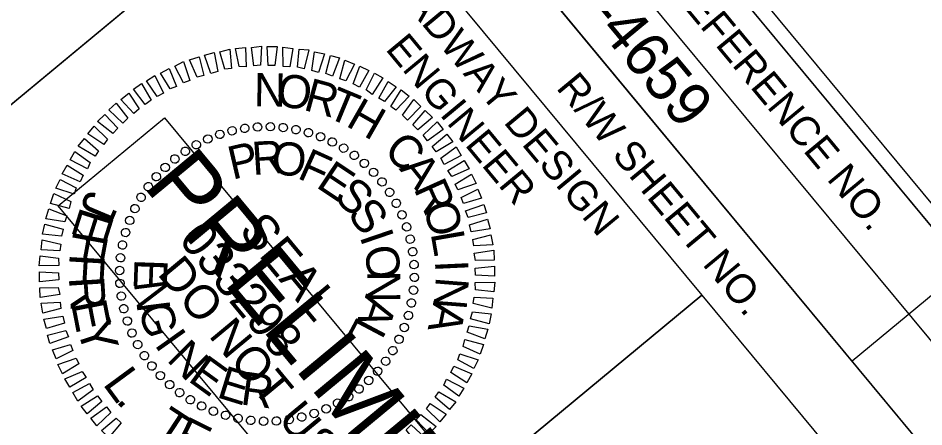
# Model space of a CAD drawing. Extents: x 2057815 to 2059783, y 687683 to 689713.
# Drawn here: x 2059495.3 to 2059649.4, y 688411.4 to 688481 of the extents above; entities that cross this region are included whole.
import ezdxf

# ---------------------------------------------------------------- set-up
doc = ezdxf.new("R2010")
doc.units = 0
for name, color, linetype in [('Sheet Data Field CELL', 7, 'Continuous'), ('Sheet Plan CELL', 7, 'Continuous'), ('Sheet Plan Layout CELL', 7, 'Continuous'), ('Sheet Plot Border Inside CELL', 7, 'Continuous'), ('Sheet Professional Seal CELL', 7, 'Continuous'), ('Sheet Sticker Preliminary CELL', 7, 'Continuous')]:
    doc.layers.add(name, color=color, linetype=linetype)

msp = doc.modelspace()

# ---------------------------------------------------------------- linework, layer by layer
at = {"layer": 'Sheet Plan CELL'}
for p, q in [((2059567.06, 688526.83), (2059694.75, 688372.83)), ((2059557.41, 688518.82), (2059685.12, 688364.85)), ((2059557.41, 688518.82), (2059685.12, 688364.85)), ((2059656.47, 688438.56), (2059637.26, 688422.56)), ((2059611.67, 688433.83), (2059525.11, 688362.04))]:
    msp.add_line(p, q, dxfattribs=at)
for points in [[(2059704.43, 688380.81), (2058746.91, 689535.49), (2057938.66, 688865.25), (2058896.16, 687710.59)], [(2057938.66, 688865.25), (2058746.88, 689535.49), (2059576.73, 688534.83), (2059461.22, 688439.03), (2059588.9, 688285.05), (2058896.16, 687710.59)], [(2059576.73, 688534.83), (2059704.43, 688380.81), (2059685.12, 688364.85), (2059557.41, 688518.82)], [(2059547.8, 688510.85), (2059611.67, 688433.83), (2059525.06, 688362.01), (2059461.22, 688439.03)], [(2059611.67, 688433.83), (2059675.5, 688356.87), (2059588.9, 688285.05), (2059525.06, 688362.01)]]:
    msp.add_lwpolyline(points, close=True, dxfattribs=at)
at = {"layer": 'Sheet Plan Layout CELL'}
msp.add_lwpolyline([(2059388.89, 688430.01), (2059541.63, 688245.83), (2059704.44, 688380.81), (2059551.69, 688565.01)], close=True, dxfattribs=at)
at = {"layer": 'Sheet Plot Border Inside CELL'}
msp.add_lwpolyline([(2057838.75, 688981.79), (2058902.21, 687699.38), (2059714.31, 688372.8), (2058650.85, 689655.23)], close=True, dxfattribs=at)
at = {"layer": 'Sheet Professional Seal CELL'}
for p, q in [((2059536.04, 688462.48), (2059536.04, 688462.48)), ((2059538.25, 688462.56), (2059538.25, 688462.56)), ((2059529.61, 688461.23), (2059529.61, 688461.23)), ((2059531.72, 688461.82), (2059531.72, 688461.82)), ((2059533.86, 688462.29), (2059533.86, 688462.29)), ((2059540.4, 688462.39), (2059540.4, 688462.39)), ((2059542.61, 688462.08), (2059542.61, 688462.08)), ((2059544.69, 688461.53), (2059544.69, 688461.53)), ((2059525.64, 688459.44), (2059525.64, 688459.44)), ((2059527.54, 688460.43), (2059527.54, 688460.43)), ((2059546.79, 688460.8), (2059546.79, 688460.8)), ((2059548.8, 688459.94), (2059548.8, 688459.94)), ((2059523.76, 688458.33), (2059523.76, 688458.33)), ((2059550.7, 688458.91), (2059550.7, 688458.91)), ((2059521.97, 688457.04), (2059521.97, 688457.04)), ((2059552.5, 688457.68), (2059552.5, 688457.68)), ((2059520.31, 688455.6), (2059520.31, 688455.6)), ((2059554.21, 688456.24), (2059554.21, 688456.24)), ((2059555.81, 688454.77), (2059555.81, 688454.77)), ((2059518.85, 688454), (2059518.85, 688454)), ((2059517.41, 688452.29), (2059517.41, 688452.29)), ((2059557.26, 688453.11), (2059557.26, 688453.11)), ((2059516.18, 688450.48), (2059516.18, 688450.48)), ((2059558.55, 688451.32), (2059558.55, 688451.32)), ((2059515.15, 688448.59), (2059515.15, 688448.59)), ((2059559.65, 688449.44), (2059559.65, 688449.44)), ((2059560.64, 688447.54), (2059560.64, 688447.54)), ((2059514.29, 688446.58), (2059514.29, 688446.58)), ((2059561.44, 688445.48), (2059561.44, 688445.48)), ((2059513.56, 688444.48), (2059513.56, 688444.48)), ((2059513.01, 688442.4), (2059513.01, 688442.4)), ((2059562.03, 688443.36), (2059562.03, 688443.36)), ((2059562.5, 688441.22), (2059562.5, 688441.22)), ((2059512.69, 688440.19), (2059512.69, 688440.19)), ((2059512.53, 688438.04), (2059512.53, 688438.04)), ((2059562.69, 688439.04), (2059562.69, 688439.04)), ((2059537.65, 688437.44), (2059537.65, 688437.44)), ((2059562.77, 688436.83), (2059562.77, 688436.83)), ((2059512.61, 688435.83), (2059512.61, 688435.83)), ((2059562.6, 688434.68), (2059562.6, 688434.68)), ((2059512.79, 688433.65), (2059512.79, 688433.65)), ((2059562.29, 688432.47), (2059562.29, 688432.47)), ((2059513.27, 688431.51), (2059513.27, 688431.51)), ((2059561.74, 688430.39), (2059561.74, 688430.39)), ((2059513.85, 688429.4), (2059513.85, 688429.4)), ((2059514.65, 688427.33), (2059514.65, 688427.33)), ((2059561.01, 688428.3), (2059561.01, 688428.3)), ((2059560.15, 688426.28), (2059560.15, 688426.28)), ((2059515.65, 688425.43), (2059515.65, 688425.43)), ((2059559.12, 688424.39), (2059559.12, 688424.39)), ((2059516.75, 688423.55), (2059516.75, 688423.55)), ((2059557.89, 688422.59), (2059557.89, 688422.59)), ((2059518.04, 688421.76), (2059518.04, 688421.76)), ((2059556.45, 688420.87), (2059556.45, 688420.87)), ((2059519.48, 688420.1), (2059519.48, 688420.1)), ((2059554.99, 688419.27), (2059554.99, 688419.27)), ((2059521.09, 688418.64), (2059521.09, 688418.64)), ((2059553.32, 688417.83), (2059553.32, 688417.83)), ((2059522.8, 688417.2), (2059522.8, 688417.2)), ((2059551.54, 688416.54), (2059551.54, 688416.54)), ((2059524.6, 688415.96), (2059524.6, 688415.96)), ((2059526.49, 688414.94), (2059526.49, 688414.94)), ((2059549.66, 688415.44), (2059549.66, 688415.44)), ((2059528.51, 688414.07), (2059528.51, 688414.07)), ((2059530.61, 688413.34), (2059530.61, 688413.34)), ((2059545.69, 688413.64), (2059545.69, 688413.64)), ((2059547.75, 688414.44), (2059547.75, 688414.44)), ((2059532.69, 688412.79), (2059532.69, 688412.79)), ((2059534.89, 688412.48), (2059534.89, 688412.48)), ((2059537.04, 688412.32), (2059537.04, 688412.32)), ((2059539.25, 688412.39), (2059539.25, 688412.39)), ((2059541.44, 688412.58), (2059541.44, 688412.58)), ((2059543.58, 688413.06), (2059543.58, 688413.06))]:
    msp.add_line(p, q, dxfattribs=at)
for points in [[(2059528.09, 688471.6), (2059527, 688474.72), (2059528.67, 688475.13), (2059529.26, 688471.92)], [(2059530.5, 688472.3), (2059529.64, 688475.29), (2059531.31, 688475.7), (2059531.61, 688472.44)], [(2059532.92, 688472.75), (2059532.29, 688475.86), (2059534, 688475.98), (2059534.12, 688472.71)], [(2059535.42, 688472.87), (2059535, 688476.03), (2059536.72, 688476.23), (2059536.56, 688472.98)], [(2059537.84, 688472.93), (2059537.68, 688476.17), (2059539.38, 688476.16), (2059538.98, 688472.96)], [(2059540.42, 688472.79), (2059540.37, 688476.07), (2059542.05, 688475.84), (2059541.54, 688472.69)], [(2059542.82, 688472.64), (2059543.11, 688475.74), (2059544.8, 688475.58), (2059543.96, 688472.36)], [(2059545.29, 688472.09), (2059545.76, 688475.28), (2059547.43, 688474.91), (2059546.39, 688471.77)], [(2059523.43, 688470.01), (2059521.95, 688472.81), (2059523.45, 688473.6), (2059524.5, 688470.37)], [(2059525.76, 688470.97), (2059524.47, 688473.93), (2059526.08, 688474.42), (2059526.92, 688471.21)], [(2059547.65, 688471.59), (2059548.44, 688474.64), (2059550, 688474.24), (2059548.82, 688471.12)], [(2059550.02, 688470.69), (2059550.92, 688473.84), (2059552.52, 688473.15), (2059551.09, 688470.34)], [(2059521.17, 688468.98), (2059519.5, 688471.62), (2059521.03, 688472.44), (2059522.23, 688469.34)], [(2059552.32, 688469.8), (2059553.45, 688472.82), (2059554.98, 688472.07), (2059553.37, 688469.24)], [(2059518.95, 688467.66), (2059517.14, 688470.31), (2059518.58, 688471.25), (2059520.04, 688468.23)], [(2059554.53, 688468.78), (2059555.93, 688471.63), (2059557.35, 688470.86), (2059555.56, 688468.01)], [(2059556.71, 688467.4), (2059558.28, 688470.2), (2059559.62, 688469.3), (2059557.65, 688466.82)], [(2059516.94, 688466.32), (2059514.95, 688468.89), (2059516.28, 688469.86), (2059517.93, 688467.01)], [(2059558.74, 688465.97), (2059560.5, 688468.79), (2059561.85, 688467.7), (2059559.6, 688465.32)], [(2059514.99, 688464.76), (2059512.8, 688467.17), (2059514.11, 688468.25), (2059515.91, 688465.53)], [(2059560.7, 688464.47), (2059562.65, 688467.13), (2059563.82, 688465.96), (2059561.58, 688463.65)], [(2059513.1, 688463.13), (2059510.71, 688465.38), (2059511.96, 688466.54), (2059513.96, 688463.97)], [(2059511.44, 688461.37), (2059508.83, 688463.42), (2059510.04, 688464.62), (2059512.24, 688462.29)], [(2059562.46, 688462.82), (2059564.57, 688465.28), (2059565.81, 688464.1), (2059563.34, 688461.99)], [(2059509.88, 688459.49), (2059507.14, 688461.31), (2059508.25, 688462.62), (2059510.5, 688460.39)], [(2059564.25, 688461.05), (2059566.59, 688463.32), (2059567.61, 688462.02), (2059564.98, 688460.1)], [(2059565.74, 688459.17), (2059568.24, 688461.25), (2059569.26, 688459.95), (2059566.47, 688458.22)], [(2059508.42, 688457.49), (2059505.49, 688459.22), (2059506.57, 688460.51), (2059509, 688458.43)], [(2059507.08, 688455.35), (2059504.13, 688456.86), (2059504.97, 688458.28), (2059507.57, 688456.4)], [(2059567.22, 688457.15), (2059569.85, 688459.07), (2059570.67, 688457.61), (2059567.83, 688456.1)], [(2059568.45, 688455.05), (2059571.2, 688456.75), (2059572.06, 688455.32), (2059569.1, 688454.03)], [(2059505.84, 688453.15), (2059502.81, 688454.47), (2059503.62, 688455.99), (2059506.37, 688454.24)], [(2059504.83, 688451.01), (2059501.69, 688452.05), (2059502.47, 688453.54), (2059505.18, 688452.08)], [(2059569.65, 688452.74), (2059572.47, 688454.43), (2059573.25, 688452.86), (2059570.13, 688451.77)], [(2059570.68, 688450.47), (2059573.55, 688451.88), (2059574.15, 688450.36), (2059571.08, 688449.44)], [(2059503.96, 688448.61), (2059500.81, 688449.43), (2059501.36, 688451.12), (2059504.29, 688449.78)], [(2059571.43, 688448.17), (2059574.58, 688449.29), (2059575.02, 688447.83), (2059571.89, 688447.06)], [(2059503.22, 688446.3), (2059500.04, 688446.84), (2059500.54, 688448.5), (2059503.56, 688447.36)], [(2059502.67, 688443.9), (2059499.47, 688444.23), (2059499.84, 688445.9), (2059502.99, 688445.07)], [(2059572.13, 688445.83), (2059575.2, 688446.75), (2059575.65, 688445.11), (2059572.41, 688444.63)], [(2059572.71, 688443.32), (2059575.77, 688444.1), (2059576.07, 688442.41), (2059572.86, 688442.21)], [(2059502.4, 688441.4), (2059499.22, 688441.56), (2059499.38, 688443.25), (2059502.54, 688442.49)], [(2059572.92, 688440.96), (2059576.27, 688441.47), (2059576.29, 688439.8), (2059573.16, 688439.73)], [(2059502.21, 688438.9), (2059498.9, 688438.82), (2059499.05, 688440.51), (2059502.18, 688440.11)], [(2059502.23, 688436.45), (2059498.93, 688436.12), (2059498.94, 688437.82), (2059502.16, 688437.62)], [(2059573.07, 688438.43), (2059576.37, 688438.76), (2059576.35, 688437.05), (2059573.14, 688437.25)], [(2059502.38, 688433.91), (2059499.03, 688433.41), (2059499.01, 688435.08), (2059502.14, 688435.14)], [(2059573.09, 688435.97), (2059576.4, 688436.06), (2059576.24, 688434.37), (2059573.12, 688434.76)], [(2059572.89, 688433.47), (2059576.08, 688433.32), (2059575.92, 688431.63), (2059572.76, 688432.38)], [(2059502.58, 688431.55), (2059499.53, 688430.77), (2059499.23, 688432.47), (2059502.44, 688432.66)], [(2059503.17, 688429.04), (2059500.1, 688428.12), (2059499.65, 688429.76), (2059502.89, 688430.24)], [(2059572.63, 688430.98), (2059575.83, 688430.64), (2059575.46, 688428.97), (2059572.3, 688429.8)], [(2059572.08, 688428.58), (2059575.26, 688428.03), (2059574.75, 688426.37), (2059571.73, 688427.51)], [(2059503.87, 688426.71), (2059500.71, 688425.58), (2059500.28, 688427.04), (2059503.41, 688427.81)], [(2059504.62, 688424.4), (2059501.75, 688423), (2059501.15, 688424.51), (2059504.22, 688425.43)], [(2059571.33, 688426.27), (2059574.49, 688425.44), (2059573.94, 688423.75), (2059571.01, 688425.09)], [(2059505.65, 688422.14), (2059502.83, 688420.45), (2059502.05, 688422.01), (2059505.17, 688423.1)], [(2059570.47, 688423.86), (2059573.6, 688422.82), (2059572.83, 688421.33), (2059570.12, 688422.79)], [(2059506.85, 688419.82), (2059504.1, 688418.13), (2059503.24, 688419.56), (2059506.2, 688420.84)], [(2059569.45, 688421.72), (2059572.49, 688420.41), (2059571.67, 688418.88), (2059568.93, 688420.63)], [(2059568.22, 688419.53), (2059571.17, 688418.01), (2059570.32, 688416.6), (2059567.73, 688418.47)], [(2059508.08, 688417.72), (2059505.45, 688415.8), (2059504.62, 688417.26), (2059507.46, 688418.77)], [(2059509.56, 688415.7), (2059507.05, 688413.63), (2059506.04, 688414.93), (2059508.83, 688416.66)], [(2059566.88, 688417.38), (2059569.81, 688415.65), (2059568.73, 688414.37), (2059566.3, 688416.44)], [(2059511.05, 688413.82), (2059508.71, 688411.55), (2059507.69, 688412.86), (2059510.32, 688414.78)], [(2059565.42, 688415.39), (2059568.16, 688413.57), (2059567.04, 688412.25), (2059564.8, 688414.48)], [(2059563.86, 688413.51), (2059566.47, 688411.45), (2059565.26, 688410.25), (2059563.06, 688412.59)], [(2059512.84, 688412.06), (2059510.73, 688409.59), (2059509.49, 688410.77), (2059511.96, 688412.88)], [(2059562.2, 688411.74), (2059564.58, 688409.5), (2059563.34, 688408.34), (2059561.34, 688410.9)]]:
    msp.add_lwpolyline(points, close=True, dxfattribs=at)
for centre, major_axis in [((2059531.72, 688461.81), (-0.17, 0.7)), ((2059533.87, 688462.23), (-0.109, 0.712)), ((2059536.04, 688462.47), (-0.046, 0.719)), ((2059538.23, 688462.51), (0.017, 0.72)), ((2059540.42, 688462.36), (0.079, 0.716)), ((2059542.58, 688462.03), (0.141, 0.706)), ((2059527.58, 688460.41), (-0.289, 0.659)), ((2059529.62, 688461.2), (-0.23, 0.682)), ((2059544.7, 688461.5), (0.202, 0.691)), ((2059546.77, 688460.8), (0.262, 0.671)), ((2059525.62, 688459.44), (-0.345, 0.632)), ((2059548.77, 688459.91), (0.319, 0.645)), ((2059550.69, 688458.86), (0.374, 0.615)), ((2059521.98, 688457.02), (-0.45, 0.562)), ((2059523.75, 688458.31), (-0.399, 0.599)), ((2059552.51, 688457.64), (0.427, 0.58)), ((2059520.33, 688455.58), (-0.497, 0.521)), ((2059554.21, 688456.27), (0.476, 0.541)), ((2059518.82, 688454), (-0.541, 0.476)), ((2059555.79, 688454.75), (0.521, 0.497)), ((2059557.23, 688453.11), (0.562, 0.45)), ((2059517.44, 688452.3), (-0.58, 0.427)), ((2059558.52, 688451.34), (0.599, 0.399)), ((2059516.23, 688450.48), (-0.615, 0.374)), ((2059559.65, 688449.47), (0.632, 0.345)), ((2059515.17, 688448.56), (-0.645, 0.319)), ((2059514.29, 688446.56), (-0.671, 0.262)), ((2059560.62, 688447.5), (0.659, 0.289)), ((2059561.41, 688445.46), (0.682, 0.23)), ((2059513.58, 688444.49), (-0.691, 0.202)), ((2059562.02, 688443.36), (0.7, 0.17)), ((2059513.06, 688442.36), (-0.706, 0.141)), ((2059512.72, 688440.2), (-0.716, 0.079)), ((2059562.44, 688441.22), (0.712, 0.109)), ((2059562.68, 688439.04), (0.719, 0.046)), ((2059512.58, 688438.02), (-0.72, 0.017)), ((2059512.62, 688435.83), (-0.719, -0.046)), ((2059562.72, 688436.85), (0.72, -0.017)), ((2059562.58, 688434.67), (0.716, -0.079)), ((2059512.86, 688433.66), (-0.712, -0.109)), ((2059562.24, 688432.51), (0.706, -0.141)), ((2059513.28, 688431.51), (-0.7, -0.17)), ((2059513.89, 688429.41), (-0.682, -0.23)), ((2059561.72, 688430.38), (0.691, -0.202)), ((2059561.01, 688428.31), (0.671, -0.262)), ((2059514.68, 688427.37), (-0.659, -0.289)), ((2059560.13, 688426.31), (0.645, -0.319)), ((2059515.64, 688425.41), (-0.632, -0.345)), ((2059516.78, 688423.53), (-0.599, -0.399)), ((2059559.07, 688424.39), (0.615, -0.374)), ((2059518.07, 688421.77), (-0.562, -0.45)), ((2059557.85, 688422.58), (0.58, -0.427)), ((2059519.51, 688420.12), (-0.521, -0.497)), ((2059556.48, 688420.87), (0.541, -0.476)), ((2059521.09, 688418.6), (-0.476, -0.541)), ((2059554.97, 688419.29), (0.497, -0.521)), ((2059522.79, 688417.23), (-0.427, -0.58)), ((2059553.32, 688417.85), (0.45, -0.562)), ((2059524.61, 688416.01), (-0.374, -0.615)), ((2059549.68, 688415.43), (0.345, -0.632)), ((2059551.55, 688416.56), (0.399, -0.599)), ((2059526.52, 688414.96), (-0.319, -0.645)), ((2059528.53, 688414.07), (-0.262, -0.671)), ((2059547.72, 688414.47), (0.289, -0.659)), ((2059530.6, 688413.37), (-0.202, -0.691)), ((2059532.72, 688412.85), (-0.141, -0.706)), ((2059534.88, 688412.51), (-0.079, -0.716)), ((2059539.25, 688412.41), (0.046, -0.719)), ((2059541.43, 688412.64), (0.109, -0.712)), ((2059543.57, 688413.07), (0.17, -0.7)), ((2059545.68, 688413.68), (0.23, -0.682)), ((2059537.07, 688412.36), (-0.017, -0.72))]:
    msp.add_ellipse(centre, major_axis=major_axis, ratio=0.999708, dxfattribs=at)
at = {"layer": 'Sheet Sticker Preliminary CELL'}
msp.add_lwpolyline([(2059502.14, 688449.04), (2059520.23, 688464.04), (2059614.06, 688350.89), (2059595.97, 688335.89)], close=True, dxfattribs=at)

# ---------------------------------------------------------------- texts
at = {"layer": 'Sheet Data Field CELL'}
msp.add_text('B-4659', height=7.5, rotation=309.6672, dxfattribs=at).set_placement((2059587.67, 688486.66))
at = {"layer": 'Sheet Plan CELL'}
for s, height, p in [('PROJECT REFERENCE NO.', 5.0001, (2059584.18, 688512.18)), ('ROADWAY DESIGN', 5.0001, (2059554.55, 688491.27)), ('ENGINEER', 5, (2059557.68, 688475.7)), ('R/W SHEET NO.', 5.0001, (2059586.73, 688469.08))]:
    msp.add_text(s, height=height, rotation=309.6672, dxfattribs=at).set_placement(p)
at = {"layer": 'Sheet Professional Seal CELL'}
for s, height, rotation, p in [('N', 5.64, 359.0907, (2059535.38, 688466.02)), ('O', 5.64, 351.8889, (2059539.08, 688466.1)), ('R', 5.64, 344.6877, (2059543.67, 688465.42)), ('T', 5.64, 337.487, (2059547.53, 688464.21)), ('H', 5.64, 330.2867, (2059550.88, 688462.76)), ('C', 5.64, 315.8871, (2059557.27, 688458.19)), ('P', 5.64, 13.0661, (2059531.76, 688453.47)), ('R', 5.64, 3.7069, (2059535.24, 688454.28)), ('O', 5.64, 354.3484, (2059538.25, 688454.5)), ('F', 5.64, 335.6342, (2059542.62, 688453.84)), ('E', 5.64, 326.2783, (2059545.82, 688452.33)), ('A', 5.64, 308.6875, (2059560.02, 688455.34)), ('S', 5.64, 316.9228, (2059548.83, 688450.35)), ('R', 5.64, 294.2883, (2059562.55, 688451.98)), ('J', 6, 247.2287, (2059507.17, 688451.91)), ('S', 5.64, 307.5676, (2059551.17, 688447.61)), ('O', 5.64, 287.0884, (2059564.11, 688448.92)), ('E', 6, 252.4865, (2059505.98, 688449.05)), ('SEAL', 5.998, 309.6672, (2059532.69, 688444.75)), ('033298', 5.998, 309.6672, (2059522.45, 688443.22)), ('F', 6, 259.5958, (2059504.78, 688445.04)), ('I', 5.64, 288.8568, (2059553.37, 688443.85)), ('L', 5.64, 279.8881, (2059565.49, 688444.35)), ('O', 5.64, 279.5007, (2059554.11, 688441.87)), ('F', 6, 266.6124, (2059504.1, 688440.97)), ('E', 5.64, 267.9441, (2059515.13, 688440.07)), ('I', 5.64, 272.6873, (2059566.23, 688439.7)), ('R', 6, 273.629, (2059503.92, 688436.85)), ('N', 5.64, 270.1438, (2059554.71, 688438.01)), ('N', 5.64, 265.4861, (2059566.41, 688437.06)), ('N', 5.64, 277.3012, (2059514.97, 688436.04)), ('A', 5.64, 251.4275, (2059554.53, 688434.16)), ('E', 6, 281.1093, (2059504.28, 688432.46)), ('G', 5.64, 286.6574, (2059515.66, 688431.68)), ('A', 5.64, 258.2844, (2059566.02, 688432.91)), ('Y', 6, 288.2186, (2059505.15, 688428.37)), ('L', 5.64, 242.0681, (2059553.12, 688430.45)), ('I', 5.64, 305.3684, (2059518.38, 688425.42)), ('N', 5.64, 314.7236, (2059520.41, 688422.75)), ('E', 5.64, 324.079, (2059524.03, 688419.32)), ('L', 6, 306.332, (2059509.58, 688418.72)), ('E', 5.64, 342.7913, (2059528.91, 688416.49)), ('R', 5.64, 352.1486, (2059532.99, 688415.25)), ('.', 6, 312.6068, (2059511.8, 688415.76)), ('T', 6, 326.8409, (2059517.92, 688410.07)), ('E', 6, 333.6411, (2059521.3, 688407.93))]:
    msp.add_text(s, height=height, rotation=rotation, dxfattribs=at).set_placement(p)
at = {"layer": 'Sheet Sticker Preliminary CELL'}
for s, height, p in [('PRELIMINARY PLANS', 11.52, (2059516.41, 688452.43)), ('DO NOT USE FOR CONSTRUCTION', 5.76, (2059518.85, 688437.43))]:
    msp.add_text(s, height=height, rotation=309.6672, dxfattribs=at).set_placement(p)

doc.saveas('drawing.dxf')
